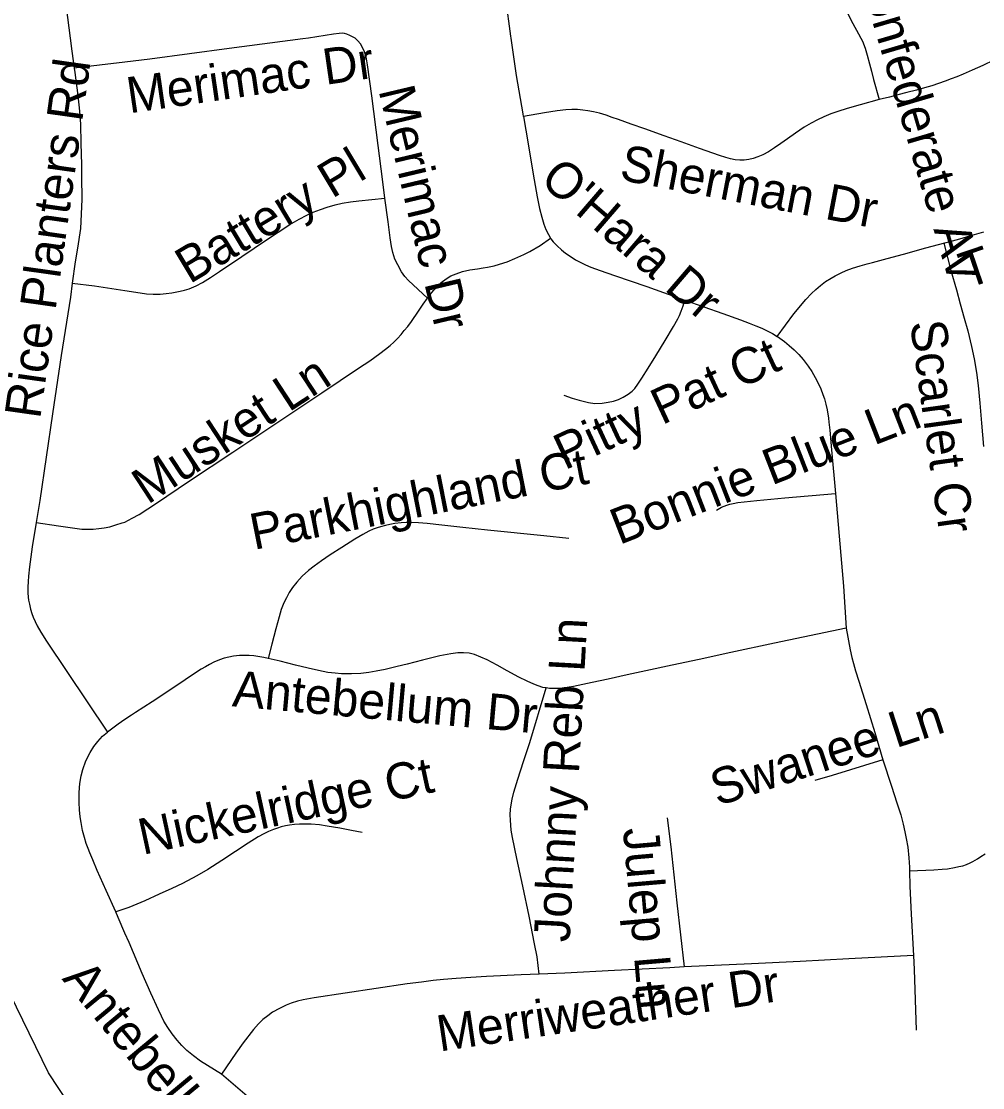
# Model space of a CAD drawing. Extents: x 1383679 to 1536984, y 460658 to 651027.
# Drawn here: x 1413802 to 1416335, y 510300 to 513110 of the extents above; entities that cross this region are included whole.
import ezdxf

# ---------------------------------------------------------------- set-up
doc = ezdxf.new("R2010")
doc.units = 0
for name, color, linetype in [('Exist Hydrographic Creek Single Shore', 7, 'Continuous'), ('Exist Road Non-System Type 51', 7, 'Continuous'), ('Exist Road Non-System Type 51 Label', 7, 'Continuous')]:
    doc.layers.add(name, color=color, linetype=linetype)

msp = doc.modelspace()

# ---------------------------------------------------------------- linework, layer by layer
at = {"layer": 'Exist Hydrographic Creek Single Shore'}
msp.add_lwpolyline([(1416110.4, 506227.3), (1416032.4, 506911.6), (1416016.4, 507371.5), (1415981.4, 507739.8), (1415957.4, 507756.6), (1415943.4, 507921.1), (1415790.4, 508167.1), (1414969, 508927.4), (1414714, 509151.7), (1414318.5, 509663.9), (1413873.4, 510339.2), (1413620, 510858)], dxfattribs=at)
at = {"layer": 'Exist Road Non-System Type 51'}
for points in [[(1413889.2, 513383.2), (1413902.2, 513285), (1413930.2, 513066), (1413934.6, 513031.4), (1413941.1, 512987.4)], [(1415939.3, 513274.4), (1415944.1, 513256.8), (1415958, 513205.3), (1415970.2, 513160.7), (1415975.6, 513141.8), (1415981, 513128.2), (1415992.9, 513105), (1416007.9, 513077.5), (1416014.1, 513066), (1416018.6, 513057.8), (1416025.4, 513039.5), (1416031, 513021.4), (1416037.1, 512998.6), (1416042, 512979), (1416047.5, 512956.7), (1416062.2, 512904.1)], [(1415125.6, 512859.9), (1415124.5, 512866.8), (1415106.9, 512968), (1415092.9, 513066), (1415092.1, 513071.3), (1415078.6, 513170.4), (1415070.8, 513235.7)], [(1414760.1, 512644.5), (1414753.3, 512694.6), (1414742, 512783.3), (1414725.4, 512914.1), (1414714.4, 512996.1), (1414710.5, 513016.6), (1414706.7, 513029.9), (1414702.3, 513039.7), (1414695.7, 513050.8), (1414688.7, 513059.4), (1414681.6, 513066), (1414667.4, 513073.4), (1414659.6, 513076.4), (1414653.2, 513078.2), (1414647.7, 513079), (1414639.2, 513078.7), (1414624.9, 513076.7), (1414558.3, 513066), (1414543.5, 513063.9), (1414349.3, 513038.8), (1414140.7, 513010.8), (1414075, 513003.1), (1413941.1, 512987.4)], [(1413941.1, 512987.4), (1413942.9, 512975.4), (1413950.9, 512915), (1413955, 512874.1), (1413957.4, 512839), (1413959, 512788.1), (1413960.3, 512733.1), (1413960.7, 512700.3), (1413961, 512641.6), (1413959.2, 512602), (1413957.5, 512564.8), (1413950, 512512.2), (1413944, 512476.8), (1413936.2, 512420.3)], [(1416365, 513008), (1416335.4, 512994), (1416307.6, 512981.6), (1416283.9, 512971), (1416266.9, 512964), (1416252.6, 512958.5), (1416236.7, 512952.7), (1416218.9, 512946.4), (1416201.5, 512940.6), (1416182.3, 512934.9), (1416160.9, 512929.1), (1416135.4, 512922.5), (1416111.4, 512916.6), (1416089.7, 512910.8), (1416062.2, 512904.1)], [(1416062.2, 512904.1), (1416012.2, 512890.4), (1415978.5, 512880.9), (1415953.7, 512873), (1415935.2, 512866.3), (1415916.6, 512858.8), (1415900.3, 512850.7), (1415883.2, 512842.3), (1415865, 512831.6), (1415841.8, 512816.1), (1415820.7, 512800.9), (1415803.3, 512788.2), (1415786.9, 512777.3), (1415770.8, 512766.8), (1415756.4, 512758.8), (1415743.3, 512753.1), (1415730.5, 512748.9), (1415719, 512746.5), (1415706.5, 512744.9), (1415695.7, 512744.9), (1415682.9, 512745.8), (1415670.6, 512748.4), (1415658.7, 512751.7), (1415642.2, 512756.6), (1415589.1, 512774.9), (1415541.1, 512792.7), (1415496.3, 512808.6), (1415444.7, 512826.7), (1415409.3, 512839.5), (1415376, 512851.4), (1415358.8, 512857.3), (1415342.8, 512863), (1415325.2, 512868.4), (1415309.7, 512872.1), (1415295.1, 512874.5), (1415281.5, 512876.7), (1415267.2, 512877.8), (1415252.4, 512877.8), (1415237, 512877.1), (1415214.3, 512874.4), (1415180.6, 512869.4), (1415125.6, 512859.9)], [(1415125.6, 512859.9), (1415137.3, 512787.7), (1415151.2, 512707.5), (1415161.4, 512647.8), (1415167.2, 512617.5), (1415173.3, 512594.6), (1415178.8, 512576.3), (1415184.6, 512561.4), (1415190.9, 512548.4), (1415196.2, 512538.9)], [(1413936.2, 512420.3), (1413994.6, 512413.4), (1414075, 512400.8), (1414115.1, 512394.6), (1414131.8, 512392.5), (1414149.6, 512391.5), (1414167.5, 512391.5), (1414184, 512392.8), (1414198.6, 512394.6), (1414220.9, 512398.9), (1414232, 512401.6), (1414244.1, 512405.8), (1414262.4, 512413.7), (1414279.1, 512421.8), (1414300.1, 512434.9), (1414323.8, 512450.7), (1414382.6, 512490.7), (1414448.2, 512534.2), (1414509.8, 512574.6), (1414534.4, 512589.3), (1414554.7, 512599.9), (1414571.4, 512607.2), (1414590.4, 512614.9), (1414607.6, 512621.1), (1414628.9, 512627), (1414647.5, 512631), (1414669.3, 512634.9), (1414691.1, 512637.4), (1414760.1, 512644.5)], [(1414872.1, 512381), (1414822.4, 512427.2), (1414812.9, 512437.7), (1414803.5, 512450.6), (1414793.7, 512468.3), (1414786.5, 512483.9), (1414780.7, 512501.4), (1414777.5, 512516.6), (1414774.1, 512539.5), (1414768.5, 512582.2), (1414760.1, 512644.5)], [(1414872.1, 512381), (1414876.4, 512387.2), (1414888.3, 512400.7), (1414899.1, 512412.8), (1414908.1, 512422.1), (1414921.7, 512431.8), (1414934.1, 512439.5), (1414947.9, 512445.4), (1414964.2, 512450.9), (1414983.9, 512455.1), (1415004.1, 512458.5), (1415019.3, 512460.7), (1415030.7, 512462.8), (1415048, 512466.4), (1415062.1, 512470.2), (1415081.9, 512476.9), (1415102.6, 512485.1), (1415126.1, 512495.9), (1415142.4, 512504.1), (1415169.6, 512519.7), (1415196.2, 512538.9)], [(1415196.2, 512538.9), (1415196.9, 512537.6), (1415203.3, 512529.2), (1415213.9, 512518.4), (1415225.5, 512508.4), (1415236.1, 512499.8), (1415250.7, 512489.7), (1415262.6, 512482), (1415276.4, 512474.5), (1415288.8, 512468.8), (1415303.1, 512462.9), (1415327.6, 512453.6), (1415364.8, 512440.4), (1415450.3, 512411.3), (1415550.5, 512375.6)], [(1415793.7, 512280.2), (1415837.4, 512339.3), (1415869.7, 512377.7), (1415884.6, 512393.4), (1415895.4, 512404.1), (1415907.6, 512414.3), (1415921.5, 512424.4), (1415936, 512433.5), (1415947.1, 512439.7), (1415962.5, 512447.8), (1415975.9, 512453.7), (1415992, 512459.5), (1416012.3, 512465.7), (1416031.1, 512471.4), (1416045.1, 512474.7), (1416084, 512485.4), (1416126.9, 512496.9), (1416185.9, 512513.1), (1416269, 512535.7), (1416308, 512546.7), (1416338.9, 512556)], [(1416232.8, 512525.6), (1416251.7, 512454.1), (1416266.3, 512403.2), (1416276.5, 512365.9), (1416286.9, 512328.2), (1416296.6, 512294.8), (1416306.4, 512253.8), (1416312.9, 512220.8), (1416318.8, 512185.1), (1416323.2, 512150.3), (1416327.8, 512103.8), (1416332, 512051), (1416337.4, 511989.7)], [(1413936.2, 512420.3), (1413931.1, 512383.7), (1413906.8, 512229.3), (1413884.2, 512075.7), (1413850.4, 511847.9), (1413841, 511789.9)], [(1413841, 511789.9), (1413900, 511780.7), (1413936.6, 511775.1), (1413961.4, 511772.4), (1413979.2, 511772.1), (1413991.2, 511772.1), (1414006.1, 511773.5), (1414020.6, 511775.8), (1414035.1, 511778.5), (1414050.5, 511783.1), (1414067.5, 511788.3), (1414075, 511790.8), (1414094.1, 511801.2), (1414112.5, 511810.9), (1414158.4, 511840.3), (1414242.7, 511897.5), (1414359.5, 511975.3), (1414486.1, 512059.5), (1414593.5, 512131.2), (1414690.6, 512196.2), (1414719.9, 512215.6), (1414747, 512235), (1414761.4, 512246), (1414773.9, 512256.1), (1414783.6, 512265), (1414793.3, 512274.9), (1414802.6, 512284.8), (1414811.2, 512295.8), (1414820.2, 512306.2), (1414830.1, 512319.7), (1414848.7, 512346.5), (1414860.7, 512364.8), (1414872.1, 512381)], [(1415231.7, 512125.3), (1415253.4, 512117.5), (1415271.9, 512111.9), (1415296.5, 512106), (1415313.4, 512103.6), (1415332.4, 512104), (1415348.5, 512106.4), (1415362.1, 512109.6), (1415375.3, 512114.2), (1415388.4, 512119.7), (1415400.9, 512127.7), (1415411.3, 512135.6), (1415418.7, 512142.9), (1415426.5, 512153.9), (1415437.5, 512170.2), (1415454, 512196.2), (1415473.8, 512228.6), (1415498.7, 512269.5), (1415520.4, 512306.2), (1415532, 512326.2), (1415536.2, 512334.8), (1415541.2, 512346.3), (1415545.9, 512360.6), (1415550.5, 512375.6)], [(1415550.5, 512375.6), (1415600.3, 512358), (1415651, 512340.3), (1415696.8, 512323.7), (1415720.3, 512314.8), (1415737.3, 512308.2), (1415753.6, 512301.5), (1415767.3, 512294.9), (1415781.6, 512287.4), (1415793.7, 512280.2)], [(1415793.7, 512280.2), (1415794.6, 512279.7), (1415813.1, 512266.7), (1415825.6, 512256.2), (1415838.7, 512244.5), (1415850.6, 512232.4), (1415862.7, 512219.2), (1415875.7, 512201.9), (1415885.1, 512187.3), (1415893.8, 512172.1), (1415901, 512158.5), (1415908.6, 512141.9), (1415914.6, 512127.2), (1415918.4, 512115.4), (1415922.2, 512101.5), (1415925.5, 512086.5), (1415928.8, 512064.5), (1415930, 512054.3), (1415932.7, 512032.7), (1415937.4, 511981.1), (1415947.5, 511866.3)], [(1415633.5, 511822.3), (1415646.8, 511830), (1415661.1, 511835.7), (1415669.5, 511838.1), (1415677.8, 511840.1), (1415690, 511842.3), (1415740.4, 511848), (1415813.7, 511854.7), (1415947.5, 511866.3)], [(1415947.5, 511866.3), (1415961.2, 511702.6), (1415968.4, 511621.8), (1415975.5, 511511.1)], [(1413841, 511789.9), (1413830.6, 511725.4), (1413823, 511672.8), (1413820.7, 511648.1), (1413819.5, 511633.9), (1413819.1, 511619.5), (1413819.1, 511604.5), (1413819.9, 511592.9), (1413820.9, 511584.5), (1413823, 511574.6), (1413825.9, 511561.4), (1413829.6, 511549.5), (1413833.5, 511539.8), (1413838.2, 511529.1), (1413843.6, 511517.3), (1413853.3, 511500.5), (1413867.8, 511476.8), (1414028.9, 511236.8)], [(1415245.2, 511747.6), (1415179, 511754.4), (1415030.8, 511769.8), (1414965.6, 511776.8), (1414910.5, 511782.4), (1414871.1, 511786.8), (1414848.6, 511788.7), (1414830.1, 511789.6), (1414816.2, 511789.4), (1414802.6, 511788.7), (1414786.3, 511787), (1414772.8, 511784.6), (1414761.3, 511782.1), (1414748.4, 511778.4), (1414740, 511775.5), (1414729.4, 511771.6), (1414718, 511766.5), (1414702.3, 511758.4), (1414680.7, 511745.6), (1414646.5, 511723.7), (1414616.2, 511704.4), (1414592.8, 511688.5), (1414573.7, 511674.6), (1414559.1, 511663.2), (1414541.9, 511648.2), (1414527.8, 511632.7), (1414516.2, 511618.4), (1414507.8, 511605.4), (1414500.3, 511591.4), (1414493.9, 511577.7), (1414486.9, 511560.2), (1414481, 511540.9), (1414472.3, 511509.3), (1414462.2, 511469.3), (1414452.5, 511431.3)], [(1415975.5, 511511.1), (1415787.1, 511471.9), (1415671.6, 511447.3), (1415588.2, 511428.9), (1415516.8, 511413.3), (1415448, 511398.7), (1415398.7, 511387.7), (1415348.3, 511376.7), (1415306.2, 511367.8), (1415257.5, 511357.3), (1415233.9, 511353.7), (1415219.1, 511352.4), (1415206.8, 511351.8), (1415194.2, 511352.2), (1415185.2, 511353.6)], [(1415975.5, 511511.1), (1415986.4, 511454.3), (1415990.9, 511433.5), (1415995, 511418.2), (1416000.6, 511398.3), (1416009, 511371), (1416028.1, 511310.1), (1416051.3, 511236.1), (1416072.4, 511164.4)], [(1414452.5, 511431.3), (1414441, 511433.8), (1414415, 511437.9), (1414402.5, 511439.2), (1414391.9, 511439.2), (1414376.7, 511438.8), (1414360.9, 511437), (1414348.5, 511434.6), (1414336.2, 511431.6), (1414324, 511427.4), (1414309.1, 511421.2), (1414298.1, 511415.5), (1414287.1, 511409.3), (1414275.8, 511402.7), (1414263.3, 511395), (1414204.2, 511354.7), (1414146.6, 511316.9), (1414102.7, 511288.6), (1414092.3, 511281.5), (1414075, 511270.1), (1414057.2, 511258), (1414028.9, 511236.8)], [(1415185.2, 511353.6), (1415176.5, 511355), (1415164.3, 511359.5), (1415152.9, 511363.9), (1415135.4, 511371.4), (1415113.4, 511382.3), (1415082.5, 511398.4), (1415056.1, 511413.3), (1415029.9, 511427.4), (1415013.2, 511435.1), (1414996.4, 511441.7), (1414981.7, 511445), (1414967.1, 511446.1), (1414951.9, 511445.9), (1414933.6, 511443.7), (1414904.6, 511437.8), (1414859.4, 511426.9), (1414818.8, 511416.5), (1414792, 511410), (1414760.3, 511402.5), (1414737.1, 511397.6), (1414717.5, 511394.2), (1414696.3, 511392), (1414672.1, 511390.6), (1414645.4, 511390.6), (1414629.1, 511392.1), (1414609.8, 511394.5), (1414585.2, 511399.1), (1414557.8, 511405.6), (1414524.8, 511413.7), (1414483.8, 511424.3), (1414452.5, 511431.3)], [(1415166.3, 510599.2), (1415161.4, 510644.7), (1415154.7, 510679.3), (1415140, 510752.2), (1415123.6, 510830.7), (1415107.4, 510904), (1415096, 510959.2), (1415092.8, 510978.9), (1415091.8, 510991.6), (1415090.9, 511005.4), (1415090.6, 511019), (1415091.4, 511033.8), (1415092.8, 511045.5), (1415095.6, 511060), (1415100.2, 511079.3), (1415110.5, 511112.9), (1415125.6, 511159.5), (1415141.6, 511209.7), (1415185.2, 511353.6)], [(1414050.5, 510763.6), (1414025.7, 510819.6), (1414001.9, 510872.2), (1413989.9, 510900.2), (1413982.5, 510918.8), (1413977.8, 510930.4), (1413973.1, 510943.9), (1413968, 510959.7), (1413963.3, 510977.9), (1413959.2, 510998.8), (1413956.8, 511013.7), (1413955, 511031.9), (1413954, 511052), (1413954.4, 511078.4), (1413956.1, 511101.8), (1413959.2, 511121.6), (1413963.7, 511139), (1413971.7, 511161.5), (1413983.1, 511183.5), (1413993.3, 511199.4), (1414003.8, 511212.8), (1414015.9, 511226.1), (1414028.9, 511236.8)], [(1416072.4, 511164.4), (1415939, 511123.1), (1415892.7, 511109.9)], [(1416072.4, 511164.4), (1416095.2, 511094.7), (1416109.1, 511051), (1416119.7, 511018.8), (1416125.8, 510994.9), (1416130.4, 510974.4), (1416133.4, 510956.4), (1416137.8, 510933.7), (1416141, 510905.9), (1416142.8, 510881.5), (1416143, 510871.8)], [(1414699.8, 510972.4), (1414671.9, 510977.5), (1414641, 510983.7), (1414608, 510989.3), (1414588, 510992.4), (1414565.9, 510994.5), (1414549.7, 510994.5), (1414534.6, 510994.5), (1414521.5, 510993.4), (1414508.2, 510991.7), (1414497.8, 510990), (1414486.8, 510987.5), (1414477, 510984.4), (1414466.3, 510980.6), (1414453.1, 510975.1), (1414441.3, 510969.2), (1414426.3, 510960.8), (1414399.9, 510944.5), (1414365.9, 510922.3), (1414330.5, 510898.6), (1414293.3, 510875.4), (1414264.1, 510858.3), (1414227, 510838.5), (1414198.1, 510824.6), (1414165.1, 510809.7), (1414127.6, 510792.7), (1414085.1, 510775.2), (1414075, 510771.8), (1414050.5, 510763.6)], [(1415504.1, 511010.9), (1415513.7, 510935), (1415529.4, 510786.8), (1415548.5, 510618.1)], [(1416143, 510871.8), (1416207.1, 510874.4), (1416228.6, 510875.7), (1416242.4, 510877), (1416260.9, 510880.2), (1416272.7, 510882.6), (1416282.7, 510885), (1416292.8, 510888.5), (1416302.2, 510892.3), (1416309.1, 510895.8), (1416321.4, 510902.8), (1416330.9, 510908.9), (1416341.7, 510916.3)], [(1416143, 510871.8), (1416143.6, 510831.3), (1416147.3, 510757.4), (1416152.7, 510648.2)], [(1414329.2, 510336), (1414274.4, 510369.9), (1414255.2, 510383.7), (1414238.2, 510398), (1414225.1, 510411.5), (1414212.6, 510425.4), (1414199.7, 510441.8), (1414188.2, 510458.4), (1414177.8, 510475.1), (1414170.9, 510488.9), (1414163.1, 510505.6), (1414143.1, 510549.4), (1414120.5, 510601), (1414085.7, 510682.4), (1414075, 510707.2), (1414057, 510748.9), (1414050.5, 510763.6)], [(1416152.7, 510648.2), (1415982.9, 510639.7), (1415854, 510632.8), (1415726.4, 510626.7), (1415548.5, 510618.1)], [(1416152.7, 510648.2), (1416154.5, 510611.5), (1416159.8, 510451.5)], [(1415166.3, 510599.2), (1415119.1, 510597.3), (1415027.7, 510592.9), (1414986.1, 510590.3), (1414947.5, 510587.9), (1414914.9, 510585.2), (1414887.1, 510582.4), (1414856.2, 510578.5), (1414819, 510573.3), (1414574, 510537), (1414544.2, 510531.7), (1414530, 510528.3), (1414513, 510522.6), (1414499.5, 510517.4), (1414482.4, 510508.9), (1414463.9, 510498.7), (1414451.2, 510489.7), (1414438.6, 510479.6), (1414426.8, 510468.4), (1414413.6, 510453.6), (1414386.1, 510417.9), (1414367.1, 510391), (1414329.2, 510336)], [(1415548.5, 510618.1), (1415510.6, 510616.3), (1415365.4, 510608.7), (1415233.9, 510601.9), (1415166.3, 510599.2)], [(1414426.6, 510247.7), (1414397.3, 510277.3), (1414329.2, 510336)]]:
    msp.add_lwpolyline(points, dxfattribs=at)

# ---------------------------------------------------------------- texts
at = {"layer": 'Exist Road Non-System Type 51 Label'}
for s, rotation, p in [('Confederate Av', 286.42, (1415997.8, 513267.6)), ('Merimac Dr', 8.2602, (1414086.6, 512867.8)), ('Rice Planters Rd', 81.9723, (1413851.4, 512060.5)), ('Merimac Dr', 283.3577, (1414742.8, 512928.9)), ('Battery Pl', 30.9642, (1414245.4, 512416.9)), ('Sherman Dr', 349.2035, (1415375.5, 512693.4)), ("O'Hara Dr", 319.3074, (1415165, 512686.7)), ('Taragate Dr', 18.7711, (1416294.4, 512405.6)), ('Scarlet Cr', 277.9025, (1416143.6, 512316.8)), ('Pitty Pat Ct', 24.933, (1415234.2, 511926.7)), ('Musket Ln', 33.2157, (1414134.7, 511835.4)), ('Bonnie Blue Ln', 21.3376, (1415377.8, 511730)), ('Parkhighland Ct', 11.2081, (1414415, 511717.2)), ('Johnny Reb Ln', 86.8554, (1415246.8, 510682.4)), ('Antebellum Dr', 354.8996, (1414355.9, 511305.4)), ('Swanee Ln', 18.035, (1415636.8, 511041.5)), ('Nickelridge Ct', 12.1739, (1414121.8, 510913.3)), ('Julep Ln', 274.9693, (1415387.3, 510982.3)), ('Antebellum Dr', 309.6917, (1413907.4, 510586.4)), ('Merriweather Dr', 8.4483, (1414904.2, 510395.2))]:
    msp.add_text(s, height=95, rotation=rotation, dxfattribs=at).set_placement(p)

doc.saveas('drawing.dxf')
